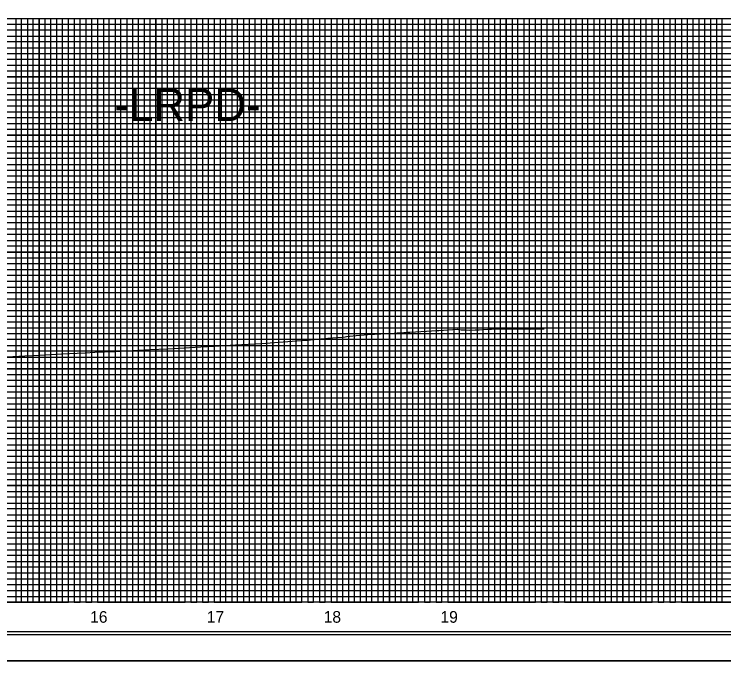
# Model space of a CAD drawing. Extents: x 573468 to 580768, y -57414 to -51768.
# Drawn here: x 579424 to 580032, y -54125 to -53560 of the extents above; entities that cross this region are included whole.
import ezdxf

# ---------------------------------------------------------------- set-up
doc = ezdxf.new("R2010")
doc.units = 0
for name, color, linetype in [('Exist Vertical Profile Ground Line', 7, 'Continuous'), ('Exist Vertical Profile Horizontal Axis Label Major', 7, 'Continuous'), ('Prop Grid Mask', 7, 'Continuous'), ('Prop PFL Text', 7, 'Continuous'), ('Sheet Cutting Line CELL', 7, 'Continuous'), ('Sheet DOT Grid CELL', 7, 'Continuous'), ('Sheet Layout Profile Border Port 2', 7, 'Continuous'), ('Sheet Plot Border Inside CELL', 7, 'Continuous'), ('Sheet Plot Border Outside CELL', 7, 'Continuous'), ('Sheet Profile CELL', 7, 'Continuous'), ('Sheet Profile Grid Major CELL', 7, 'Continuous'), ('Sheet Profile Grid Middle CELL', 7, 'Continuous'), ('Sheet Profile Grid Minor CELL', 7, 'Continuous')]:
    doc.layers.add(name, color=color, linetype=linetype)

msp = doc.modelspace()

# ---------------------------------------------------------------- linework, layer by layer
at = {"layer": 'Exist Vertical Profile Ground Line'}
msp.add_lwpolyline([(579412.38, -53853.57), (579432.88, -53852.59), (579440.19, -53852.1), (579454.54, -53851.41), (579464.24, -53850.85), (579484.53, -53849.89), (579492.91, -53849.41), (579509.78, -53848.61), (579520.21, -53848.07), (579539.77, -53847.12), (579555.38, -53846.36), (579564.67, -53845.87), (579583.65, -53844.84), (579594.68, -53844.16), (579613.39, -53843.14), (579624.32, -53842.46), (579635.67, -53841.78), (579654.3, -53840.45), (579665.79, -53839.63), (579674.75, -53839.1), (579692.57, -53837.4), (579704.74, -53836.33), (579707.41, -53836.08), (579708.41, -53835.99), (579719.48, -53834.62), (579723.51, -53834.49), (579726.69, -53834.05), (579749.14, -53832.94), (579750.7, -53832.96), (579751.77, -53832.9), (579752.81, -53832.83), (579753.7, -53832.67), (579760.89, -53832.33), (579761.77, -53832.26), (579762.28, -53832.27), (579762.66, -53832.28), (579776.88, -53831.39), (579785.65, -53830.78), (579787.56, -53830.69), (579803.61, -53829.63), (579804.43, -53830.04), (579806.73, -53830.08), (579810.85, -53830.21), (579813.54, -53830.42), (579818.7, -53830.24), (579822.06, -53830.24), (579825.69, -53829.86), (579829.55, -53829.62), (579832.7, -53829.76), (579836.84, -53829.44), (579856.32, -53829.33), (579860.16, -53829.24), (579863.48, -53829.35), (579866.08, -53829.57), (579877.75, -53829.31)], dxfattribs=at)
at = {"layer": 'Prop Grid Mask'}
msp.add_lwpolyline([(579495.21, -53613.55), (579645.21, -53613.55), (579645.21, -53663.55), (579495.21, -53663.55)], close=True, dxfattribs=at)
at = {"layer": 'Sheet Cutting Line CELL'}
for p, q in [((578678.21, -54113.55), (580362.21, -54113.55)), ((580362.21, -54113.55), (578678.21, -54113.55))]:
    msp.add_line(p, q, dxfattribs=at)
at = {"layer": 'Sheet DOT Grid CELL'}
for p, q in [((578845.21, -53563.55), (580345.1, -53563.55)), ((579445.21, -53563.55), (579445.21, -54063.55)), ((579495.21, -53563.55), (579495.21, -54063.55)), ((579545.21, -53563.55), (579545.21, -54063.55)), ((579595.21, -53563.55), (579595.21, -54063.55)), ((579645.21, -53563.55), (579645.21, -54063.55)), ((579695.21, -53563.55), (579695.21, -54063.55)), ((579745.21, -53563.55), (579745.21, -54063.55)), ((579795.21, -53563.55), (579795.21, -54063.55)), ((579845.21, -53563.55), (579845.21, -54063.55)), ((579895.21, -53563.55), (579895.21, -54063.55)), ((579945.21, -53563.55), (579945.21, -54063.55)), ((579995.21, -53563.55), (579995.21, -54063.55)), ((578845.21, -53613.55), (580345.1, -53613.55)), ((578845.21, -53663.55), (580345.1, -53663.55)), ((578845.21, -53713.55), (580345.1, -53713.55)), ((578845.21, -53763.55), (580345.1, -53763.55)), ((578845.21, -53813.55), (580345.1, -53813.55)), ((578845.21, -53863.55), (580345.1, -53863.55)), ((578845.21, -53913.55), (580345.1, -53913.55)), ((578845.21, -53963.55), (580345.1, -53963.55)), ((578845.21, -54013.55), (580345.1, -54013.55))]:
    msp.add_line(p, q, dxfattribs=at)
at = {"layer": 'Sheet Layout Profile Border Port 2'}
msp.add_lwpolyline([(578895.21, -53563.55), (580295.21, -53563.55), (580295.21, -54063.55), (578895.21, -54063.55)], close=True, dxfattribs=at)
at = {"layer": 'Sheet Plot Border Inside CELL'}
msp.add_lwpolyline([(578691.21, -54091.1), (580357.71, -54091.1), (580357.71, -53036), (578691.21, -53036)], close=True, dxfattribs=at)
at = {"layer": 'Sheet Plot Border Outside CELL'}
for points in [[(578678.21, -54113.55), (580362.21, -54113.55), (580362.21, -53013.55), (578678.21, -53013.55)], [(578678.21, -55213.55), (580362.21, -55213.55), (580362.21, -54113.55), (578678.21, -54113.55)]]:
    msp.add_lwpolyline(points, close=True, dxfattribs=at)
at = {"layer": 'Sheet Profile CELL'}
for p, q in [((578845.21, -53563.55), (580345.21, -53563.55)), ((580345.21, -54063.55), (578845.21, -54063.55)), ((578845.21, -54088.55), (580345.21, -54088.55))]:
    msp.add_line(p, q, dxfattribs=at)
msp.add_lwpolyline([(580345.21, -53038.55), (578845.21, -53038.55), (578845.21, -54088.55), (580345.21, -54088.55)], close=True, dxfattribs=at)
at = {"layer": 'Sheet Profile Grid Major CELL'}
for p, q in [((579445.21, -53563.55), (579495.21, -53563.55)), ((579545.21, -53563.55), (579595.21, -53563.55)), ((579645.21, -53563.55), (579695.21, -53563.55)), ((579745.21, -53563.55), (579795.21, -53563.55)), ((579845.21, -53563.55), (579895.21, -53563.55)), ((579945.21, -53563.55), (579995.21, -53563.55))]:
    msp.add_line(p, q, dxfattribs=at)
for points in [[(579395.21, -54063.55), (579445.21, -54063.55), (579445.21, -53563.55), (579495.21, -53563.55), (579495.21, -54063.55), (579545.21, -54063.55), (579545.21, -53563.55), (579595.21, -53563.55), (579595.21, -54063.55), (579645.21, -54063.55), (579645.21, -53563.55), (579695.21, -53563.55), (579695.21, -54063.55), (579745.21, -54063.55), (579745.21, -53563.55), (579795.21, -53563.55), (579795.21, -54063.55), (579845.21, -54063.55), (579845.21, -53563.55), (579895.21, -53563.55), (579895.21, -54063.55), (579945.21, -54063.55), (579945.21, -53563.55), (579995.21, -53563.55), (579995.21, -54063.55), (580045.21, -54063.55)], [(580345.21, -53613.55), (578845.21, -53613.55)], [(580345.21, -53663.55), (578845.21, -53663.55), (578845.21, -53713.55), (580345.21, -53713.55)], [(580345.21, -53763.55), (578845.21, -53763.55), (578845.21, -53813.55), (580345.21, -53813.55)], [(580345.21, -53863.55), (578845.21, -53863.55), (578845.21, -53913.55), (580345.21, -53913.55)], [(580345.21, -53963.55), (578845.21, -53963.55), (578845.21, -53963.55), (578845.21, -54013.55), (580345.21, -54013.55)], [(580345.21, -54063.55), (578845.21, -54063.55)]]:
    msp.add_lwpolyline(points, dxfattribs=at)
at = {"layer": 'Sheet Profile Grid Middle CELL'}
for points in [[(579420.21, -54063.55), (579470.21, -54063.55), (579470.21, -54063.55), (579470.21, -53563.55), (579520.21, -53563.55), (579520.21, -54063.55), (579570.21, -54063.55), (579570.21, -53563.55), (579620.21, -53563.55), (579620.21, -54063.55), (579670.21, -54063.55), (579670.21, -53563.55), (579720.21, -53563.55), (579720.21, -54063.55), (579770.21, -54063.55), (579770.21, -53563.55), (579820.21, -53563.55), (579820.21, -54063.55), (579870.21, -54063.55), (579870.21, -53563.55), (579920.21, -53563.55), (579920.21, -54063.55), (579970.21, -54063.55), (579970.21, -53563.55), (580020.21, -53563.55), (580020.21, -54063.55), (580070.21, -54063.55)], [(578845.21, -53588.55), (580345.21, -53588.55)], [(580345.21, -53638.55), (578845.21, -53638.55), (578845.21, -53688.55), (580345.21, -53688.55)], [(580345.21, -53738.55), (578845.21, -53738.55), (578845.21, -53788.55), (580345.21, -53788.55)], [(580345.21, -53838.55), (578845.21, -53838.55), (578845.21, -53888.55), (580345.21, -53888.55)], [(580345.21, -53938.55), (578845.21, -53938.55), (578845.21, -53988.55), (580345.21, -53988.55)], [(580345.21, -54038.55), (578845.21, -54038.55)]]:
    msp.add_lwpolyline(points, dxfattribs=at)
at = {"layer": 'Sheet Profile Grid Minor CELL'}
for p, q in [((578895.21, -53568.55), (580295.21, -53568.55)), ((580295.21, -53573.55), (578895.21, -53573.55)), ((578895.21, -53578.55), (580295.21, -53578.55)), ((580295.21, -53583.55), (578895.21, -53583.55)), ((578895.21, -53593.55), (580295.21, -53593.55)), ((580295.21, -53598.55), (578895.21, -53598.55)), ((578895.21, -53603.55), (580295.21, -53603.55)), ((580295.21, -53608.55), (578895.21, -53608.55)), ((578895.21, -53618.55), (580295.21, -53618.55)), ((580295.21, -53623.55), (578895.21, -53623.55)), ((578895.21, -53628.55), (580295.21, -53628.55)), ((580295.21, -53633.55), (578895.21, -53633.55)), ((578895.21, -53643.55), (580295.21, -53643.55)), ((580295.21, -53648.55), (578895.21, -53648.55)), ((578895.21, -53653.55), (580295.21, -53653.55)), ((580295.21, -53658.55), (578895.21, -53658.55)), ((578895.21, -53668.55), (580295.21, -53668.55)), ((580295.21, -53673.55), (578895.21, -53673.55)), ((578895.21, -53678.55), (580295.21, -53678.55)), ((580295.21, -53683.55), (578895.21, -53683.55)), ((578895.21, -53693.55), (580295.21, -53693.55)), ((580295.21, -53698.55), (578895.21, -53698.55)), ((578895.21, -53703.55), (580295.21, -53703.55)), ((580295.21, -53708.55), (578895.21, -53708.55)), ((578895.21, -53718.55), (580295.21, -53718.55)), ((580295.21, -53723.55), (578895.21, -53723.55)), ((578895.21, -53728.55), (580295.21, -53728.55)), ((580295.21, -53733.55), (578895.21, -53733.55)), ((578895.21, -53743.55), (580295.21, -53743.55)), ((580295.21, -53748.55), (578895.21, -53748.55)), ((578895.21, -53753.55), (580295.21, -53753.55)), ((580295.21, -53758.55), (578895.21, -53758.4)), ((578895.21, -53768.55), (580295.21, -53768.55)), ((580295.21, -53773.55), (578895.21, -53773.55)), ((578895.21, -53778.55), (580295.21, -53778.55)), ((580295.21, -53783.55), (578895.21, -53783.55)), ((578895.21, -53793.55), (580295.21, -53793.55)), ((580295.21, -53798.55), (578895.21, -53798.55)), ((578895.21, -53803.55), (580295.21, -53803.55)), ((580295.21, -53808.55), (578895.21, -53808.55)), ((578895.21, -53818.55), (580295.21, -53818.55)), ((580295.21, -53823.55), (578895.21, -53823.55)), ((578895.21, -53828.55), (580295.21, -53828.55)), ((580295.21, -53833.55), (578895.21, -53833.55)), ((578895.21, -53843.55), (580295.21, -53843.55)), ((580295.21, -53848.55), (578895.21, -53848.55)), ((578895.21, -53853.55), (580295.21, -53853.55)), ((580295.21, -53858.55), (578895.21, -53858.55)), ((578895.21, -53868.55), (580295.21, -53868.55)), ((580295.21, -53873.55), (578895.21, -53873.55)), ((578895.21, -53878.55), (580295.21, -53878.55)), ((580295.21, -53883.55), (578895.21, -53883.55)), ((578895.21, -53893.55), (580295.21, -53893.55)), ((580295.21, -53898.55), (578895.21, -53898.55)), ((578895.21, -53903.55), (580295.21, -53903.55)), ((580295.21, -53908.55), (578895.21, -53908.55)), ((578895.21, -53918.55), (580295.21, -53918.55)), ((580295.21, -53923.55), (578895.21, -53923.55)), ((578895.21, -53928.55), (580295.21, -53928.55)), ((580295.21, -53933.55), (578895.21, -53933.55)), ((578895.21, -53943.55), (580295.21, -53943.55)), ((580295.21, -53948.55), (578895.21, -53948.55)), ((578895.21, -53953.55), (580295.21, -53953.55)), ((580295.21, -53958.55), (578895.21, -53958.55)), ((578895.21, -53968.55), (580295.21, -53968.55)), ((580295.21, -53973.55), (578895.21, -53973.55)), ((578895.21, -53978.55), (580295.21, -53978.55)), ((580295.21, -53983.55), (578895.21, -53983.55)), ((578895.21, -53993.55), (580295.21, -53993.55)), ((580295.21, -53998.55), (578895.21, -53998.55)), ((578895.21, -54003.55), (580295.21, -54003.55)), ((580295.21, -54008.55), (578895.21, -54008.55)), ((578895.21, -54018.55), (580295.21, -54018.55)), ((580295.21, -54023.55), (578895.21, -54023.55)), ((578895.21, -54028.55), (580295.21, -54028.55)), ((580295.21, -54033.55), (578895.21, -54033.55)), ((578895.21, -54043.55), (580295.21, -54043.55)), ((580295.21, -54048.55), (578895.21, -54048.55)), ((578895.21, -54053.55), (580295.21, -54053.55)), ((578895.21, -54058.55), (580295.21, -54058.55))]:
    msp.add_line(p, q, dxfattribs=at)
for points in [[(579415.21, -53563.55), (579425.21, -53563.55)], [(579425.21, -53563.55), (579425.21, -54063.55), (579430.21, -54063.55), (579430.21, -53563.55), (579435.21, -53563.55), (579435.21, -54063.55), (579440.21, -54063.55), (579440.21, -53563.55), (579450.21, -53563.55), (579450.21, -54063.55), (579455.21, -54063.55), (579455.21, -53563.55), (579460.21, -53563.55), (579460.21, -54063.55), (579465.21, -54063.55), (579465.21, -53563.55), (579475.21, -53563.55), (579475.21, -54063.55), (579480.21, -54063.55), (579480.21, -53563.55), (579485.21, -53563.55), (579485.21, -54063.55), (579490.21, -54063.55), (579490.21, -53563.55), (579500.21, -53563.55), (579500.21, -54063.55), (579505.21, -54063.55), (579505.21, -53563.55), (579510.21, -53563.55), (579510.21, -54063.55), (579515.21, -54063.55), (579515.21, -53563.55), (579525.21, -53563.55), (579525.21, -54063.55), (579530.21, -54063.55), (579530.21, -53563.55), (579535.21, -53563.55), (579535.21, -54063.55), (579540.21, -54063.55), (579540.21, -53563.55), (579550.21, -53563.55), (579550.21, -54063.55), (579550.21, -54063.55), (579555.21, -54063.55), (579555.21, -53563.55), (579560.21, -53563.55), (579560.21, -54063.55), (579565.21, -54063.55), (579565.21, -53563.55), (579575.21, -53563.55), (579575.21, -54063.55), (579580.21, -54063.55), (579580.21, -53563.55), (579585.21, -53563.55), (579585.21, -54063.55), (579590.21, -54063.55), (579590.21, -53563.55), (579600.21, -53563.55), (579600.21, -54063.55), (579605.21, -54063.55), (579605.21, -53563.55), (579610.21, -53563.55), (579610.21, -54063.55), (579615.21, -54063.55), (579615.21, -53563.55), (579625.21, -53563.55), (579625.21, -54063.55), (579630.21, -54063.55), (579630.21, -53563.55), (579635.21, -53563.55), (579635.21, -54063.55), (579640.21, -54063.55), (579640.21, -53563.55), (579650.21, -53563.55), (579650.21, -54063.55), (579655.21, -54063.55), (579655.21, -53563.55), (579660.21, -53563.55), (579660.21, -54063.55), (579665.21, -54063.55), (579665.21, -53563.55), (579675.21, -53563.55), (579675.21, -54063.55), (579680.21, -54063.55), (579680.21, -53563.55), (579685.21, -53563.55), (579685.21, -54063.55), (579690.21, -54063.55), (579690.21, -53563.55), (579700.21, -53563.55), (579700.21, -54063.55), (579704.91, -54063), (579705.21, -54063.55), (579705.21, -53563.55), (579710.21, -53563.55), (579710.21, -54063.55), (579715.21, -54063.55), (579715.21, -53563.55), (579725.21, -53563.55), (579725.21, -54063.55), (579730.21, -54063.55)], [(579730.21, -54063.55), (579730.21, -53563.55), (579735.21, -53563.55), (579735.21, -54063.55), (579740.21, -54063.55), (579740.21, -53563.55), (579750.21, -53563.55), (579750.21, -54063.55), (579755.21, -54063.55), (579755.21, -53563.55), (579760.21, -53563.55), (579760.21, -54063.55), (579765.21, -54063.55), (579765.21, -53563.55), (579775.21, -53563.55), (579775.21, -54063.55), (579780.21, -54063.55), (579780.21, -53563.55), (579785.21, -53563.55), (579785.21, -54063.55), (579790.21, -54063.55), (579790.21, -53563.55), (579800.21, -53563.55), (579800.21, -54063.55), (579805.21, -54063.55), (579805.21, -53563.55), (579810.21, -53563.55), (579810.21, -54063.55), (579815.21, -54063.55), (579815.21, -53563.55), (579825.21, -53563.55), (579825.21, -54063.55), (579830.21, -54063.55), (579830.21, -53563.55), (579835.21, -53563.55), (579835.21, -54063.55), (579840.21, -54063.55), (579840.21, -53563.55), (579850.21, -53563.55), (579850.21, -54063.55), (579855.21, -54063.55), (579855.21, -53563.55), (579860.21, -53563.55), (579860.21, -54063.55), (579865.21, -54063.55), (579865.21, -53563.55), (579875.21, -53563.55), (579875.21, -54063.55), (579880.21, -54063.55), (579880.21, -53563.55), (579885.21, -53563.55), (579885.21, -54063.55), (579890.21, -54063.55), (579890.21, -53563.55), (579900.21, -53563.55), (579900.21, -54063.55), (579905.21, -54063.55), (579905.21, -53563.55), (579910.21, -53563.55), (579910.21, -54063.55), (579915.21, -54063.55), (579915.21, -53563.55), (579925.21, -53563.55), (579925.21, -54063.55), (579930.21, -54063.55), (579930.21, -53563.55), (579935.21, -53563.55), (579935.21, -54063.55), (579940.21, -54063.55), (579940.21, -53563.55), (579950.21, -53563.55), (579950.21, -54063.55), (579955.21, -54063.55), (579955.21, -53563.55), (579960.21, -53563.55), (579960.21, -54063.55), (579965.21, -54063.55), (579965.21, -53563.55), (579975.21, -53563.55), (579975.21, -54063.55), (579980.21, -54063.55), (579980.21, -53563.55), (579985.21, -53563.55), (579985.21, -54063.55), (579990.21, -54063.55), (579990.21, -53563.55), (580000.21, -53563.55), (580000.21, -54063.55), (580005.21, -54063.55), (580005.21, -53563.55), (580010.21, -53563.55), (580010.21, -54063.55), (580015.21, -54063.55), (580015.21, -53563.55), (580025.21, -53563.55), (580025.21, -54063.55), (580030.21, -54063.55), (580030.21, -53563.55), (580035.21, -53563.55)]]:
    msp.add_lwpolyline(points, dxfattribs=at)

# ---------------------------------------------------------------- texts
at = {"layer": 'Exist Vertical Profile Horizontal Axis Label Major'}
for s, p in [('16', (579488.9, -54081.05)), ('17', (579588.75, -54081.05)), ('18', (579688.88, -54081.05)), ('19', (579788.92, -54081.05))]:
    msp.add_text(s, height=10, dxfattribs=at).set_placement(p)
at = {"layer": 'Prop PFL Text'}
msp.add_text('-LRPD-', height=28.125, dxfattribs=at).set_placement((579509.53, -53651.44))

doc.saveas('drawing.dxf')
